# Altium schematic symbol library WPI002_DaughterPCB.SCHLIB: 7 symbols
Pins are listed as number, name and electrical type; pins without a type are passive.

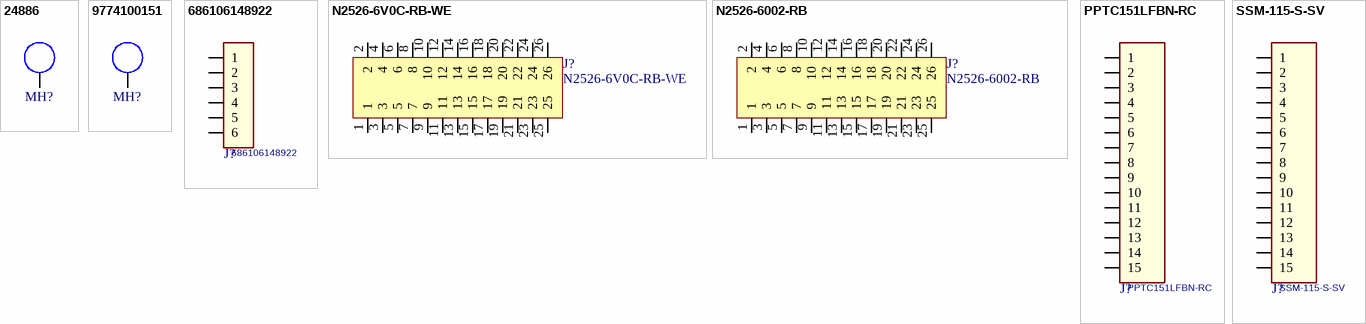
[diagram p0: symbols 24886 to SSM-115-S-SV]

## 24886
designator MH?  (value not drawn)
SM STANDOFF WITH T&R 10MM; Manufacturer: Keystone Electronics
footprint 24886
pins: 1

## 9774100151
designator MH?  (value not drawn)
RND STNDFF M2.5X0.45 STEEL 10MM; Manufacturer: Wurth Electronics; Manufacturer Part Number: 9774100151R; Description: Spacer, Smt Round, Steel, M2.5, 10Mm; Plating: Tin; Threaded/Unthreaded: Threaded; Outside Diameter: 0.201inch
footprint 9774100151
pins: 1

## 686106148922
designator J?
CONN 1MM HORZ BOTTOM SMD 6POS; Manufacturer: Wurth Electronics; Actuator Material: Nylon,Polyamide; Voltage Rating: 100V; Current Rating: 1A; Number of Positions: 6; Gender: Receptacle; Wire/Cable Type: Straight; Pitch: 0.039inch
footprint 686106148922
pins: 1, 2, 3, 4, 5, 6

## N2526-6V0C-RB-WE
designator J?
CONN HEADER SMD 26POS 2.54MM; Manufacturer: 3M; Number of Contacts: 26; Max Current Rating: 1.75A; Gender: Male; Connector Type: Male Pin; Row Spacing: 0.1inch; Approvals: UL
footprint 3M\N2526-6V0C-RB-WE
pins: 1, 2, 3, 4, 5, 6, 7, 8, 9, 10, 11, 12, 13, 14, 15, 16, 17, 18, 19, 20, 21, 22, 23, 24, 25, 26

## N2526-6002-RB
designator J?
CONN HEADER VERT 26POS 2.54MM; Manufacturer: 3M; Manufacturer Part Number: N2526-6002RB; Number of Contacts: 26; Gender: Male; Max Current Rating: 2A; Connector Type: Male Pin; Insulation Resistance: 1GR; Mating Cycles: 200; Working Voltage: 350V; Contact Resistance: 20mR; RMS Current (Irms): 1A; Row Spacing: 0.1inch; Contact Post Length: 2.84mm; Hole Diameter: 0.89mm; Approvals: UL
footprint 3M\N2526-6002-RB
pins: 1, 2, 3, 4, 5, 6, 7, 8, 9, 10, 11, 12, 13, 14, 15, 16, 17, 18, 19, 20, 21, 22, 23, 24, 25, 26

## PPTC151LFBN-RC
designator J?
CONN HDR 15POS 0.1 TIN PCB; Manufacturer: Sullins; Number of Positions: 15; Connector Type: Header; Pitch: 0.1inch
footprint PPTC151LFBN-RC
pins: 1, 2, 3, 4, 5, 6, 7, 8, 9, 10, 11, 12, 13, 14, 15

## SSM-115-S-SV
designator J?
CONN RCPT 15POS 0.1 GOLD SMD; Manufacturer: Samtec; Number of Contacts: 15; Gender: Female; Connector Type: Receptacle; Pitch: 0.1inch
footprint SSM-115-S-SV
pins: 1, 2, 3, 4, 5, 6, 7, 8, 9, 10, 11, 12, 13, 14, 15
